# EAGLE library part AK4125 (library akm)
Asynchronous Sample Rate Converter with PLL High Performance, 24-Bit, 192 kHz
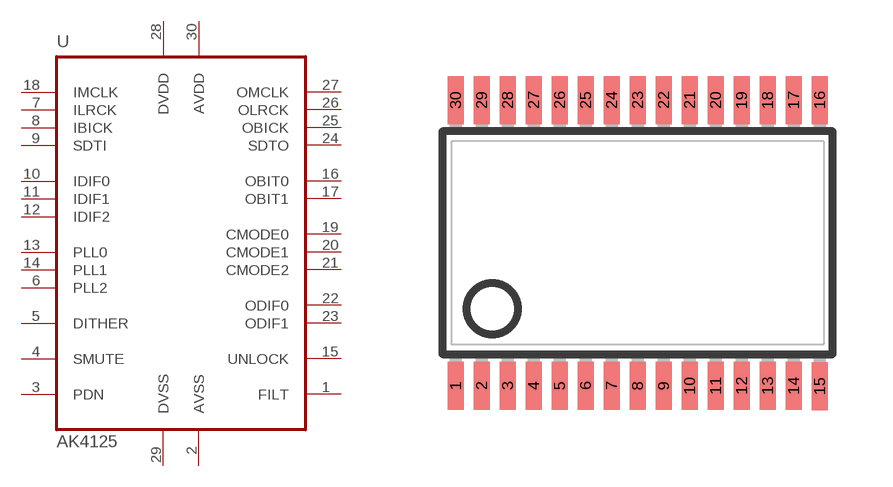
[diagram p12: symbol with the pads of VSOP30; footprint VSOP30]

Designator prefix U

## AK4125  [VSOP30]
1  FILT  out
2  AVSS  pwr
3  PDN  in
4  SMUTE  in
5  DITHER  in
6  PLL2  in
7  ILRCK
8  IBICK
9  SDTI  in
10  IDIF0  in
11  IDIF1  in
12  IDIF2  in
13  PLL0  in
14  PLL1  in
15  UNLOCK  out
16  OBIT0  in
17  OBIT1  in
18  IMCLK  in
19  CMODE0  in
20  CMODE1  in
21  CMODE2  in
22  ODIF0  in
23  ODIF1  in
24  SDTO  out
25  OBICK
26  OLRCK
27  OMCLK  in
28  DVDD  pwr
29  DVSS  pwr
30  AVDD  pwr

## Footprint VSOP30 (pad centres in mm)
VSOP30 9.7 x 5.6 mm, pitch .65 mm
smd 0.4 x 1.2: 1 -4.55,-3.57; 2 -3.9,-3.57; 3 -3.25,-3.57; 4 -2.6,-3.57; 5 -1.95,-3.57; 6 -1.3,-3.57; 7 -0.65,-3.57; 8 0,-3.57; 9 0.65,-3.57; 10 1.3,-3.57; 11 1.95,-3.57; 12 2.6,-3.57; 13 3.25,-3.57; 14 3.9,-3.57; 15 4.55,-3.58; 16 4.55,3.57; 17 3.9,3.57; 18 3.25,3.57; 19 2.6,3.57; 20 1.95,3.57; 21 1.3,3.57; 22 0.65,3.57; 23 0,3.57; 24 -0.65,3.57; 25 -1.3,3.57; 26 -1.95,3.57; 27 -2.6,3.57; 28 -3.25,3.57; 29 -3.9,3.57; 30 -4.55,3.57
